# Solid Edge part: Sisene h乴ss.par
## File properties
Author: Türk
Template: Iso Part.par
Last saved by: Türk
Revision: 9
Application: Solid Edge
Accuracy: 0,990
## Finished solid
Body 1: sheet body, 2 faces, 20 edges, 20 vertices.
  Faces by surface: plane 2
  Edges by curve: line 20
Body 2: solid body, 10 faces, 10 edges, 0 vertices.
  Faces by surface: cylinder 4, plane 4, cone 2
  Edges by curve: circle 10
Bounding box of the edges (mm): 65.000 x 50.000 x 65.000, from (-32.5, 0, -32.5) to (32.5, 50, 32.5).
Cylindrical faces by radius (mm): R27.5 x1, R30 x1, R32.5 x2
Conical faces (half-angle, radius in mm at the cone's reference point): 45 deg R27.5 x1, 45 deg R28.5 x1
Planar faces by outward normal: +y 2, -y 2
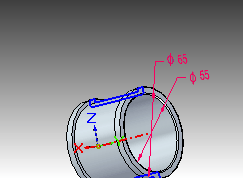
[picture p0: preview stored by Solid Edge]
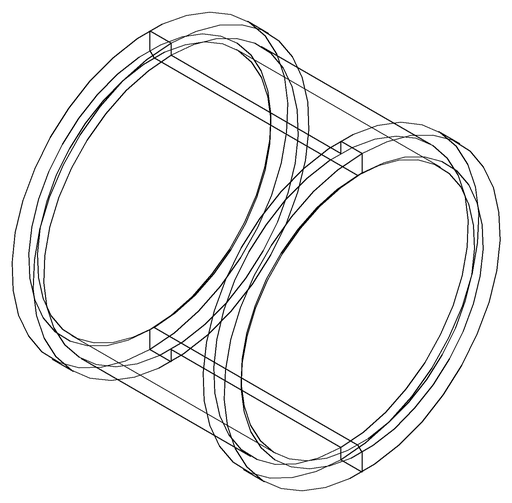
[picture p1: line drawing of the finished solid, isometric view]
